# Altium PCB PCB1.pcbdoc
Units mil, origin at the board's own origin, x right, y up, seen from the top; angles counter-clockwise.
Board outline 2455.27 x 2908.05 mil, 4 copper layers (Top Layer, Inner1, Inner2, Bottom Layer); 58 components, 37 nets, 190 pads, 225 vias.
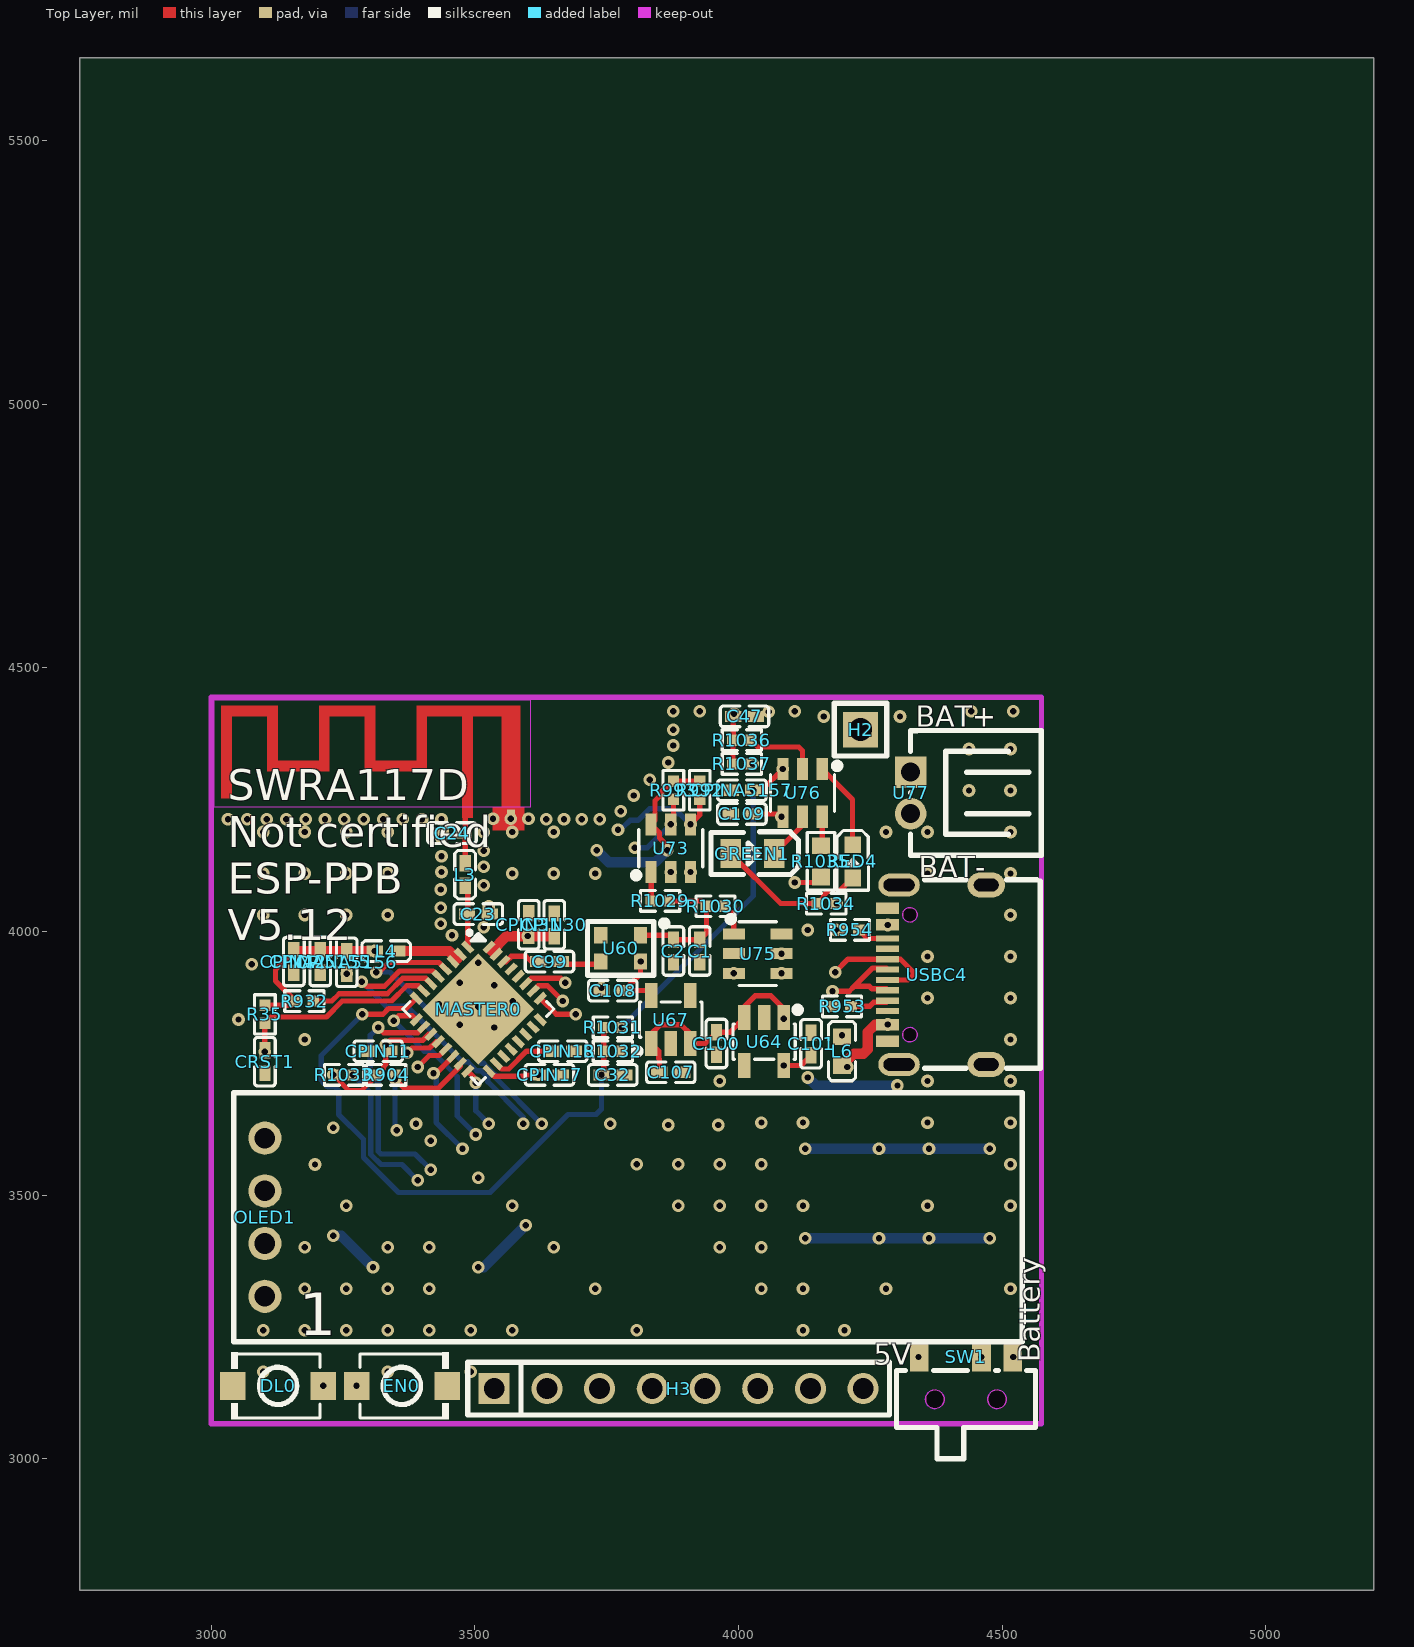
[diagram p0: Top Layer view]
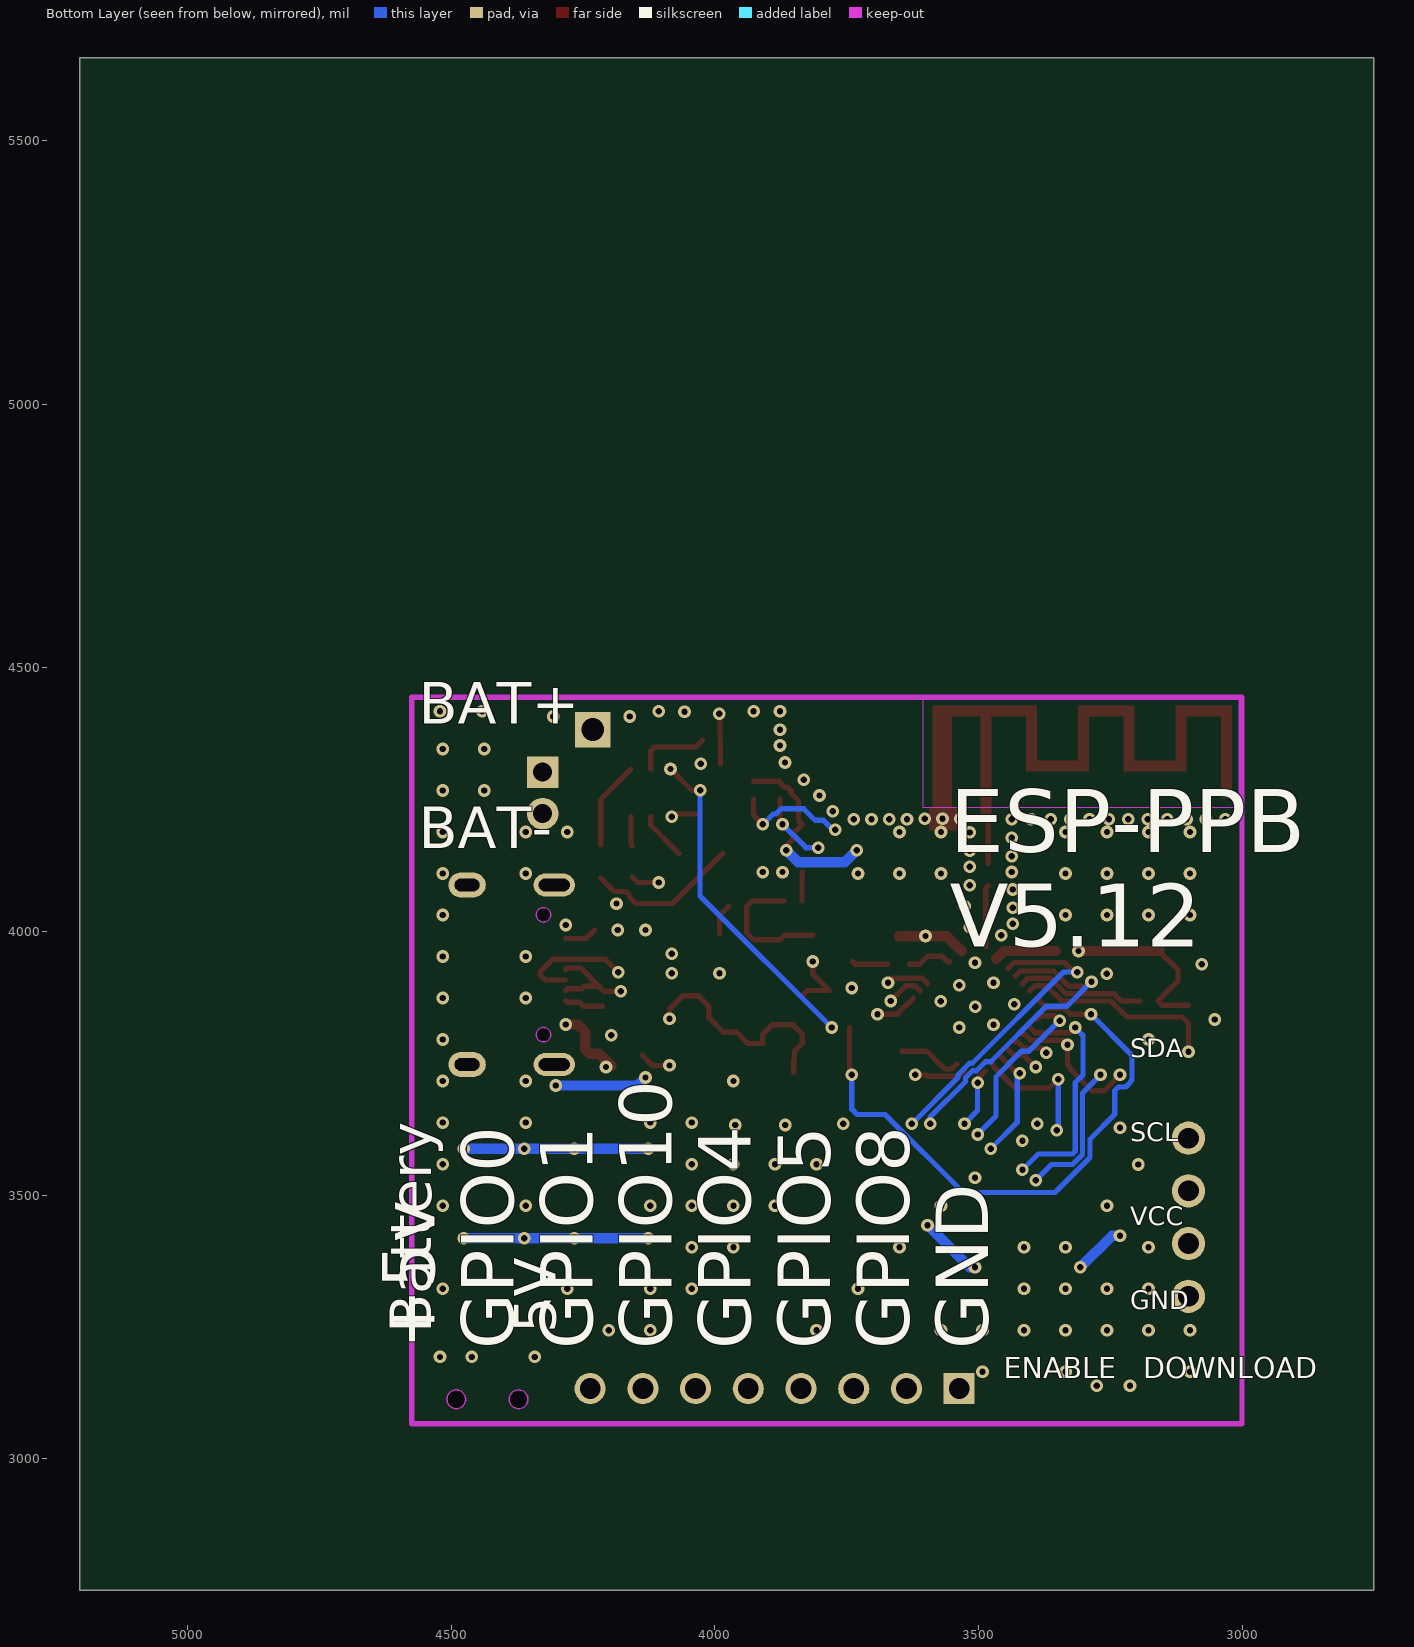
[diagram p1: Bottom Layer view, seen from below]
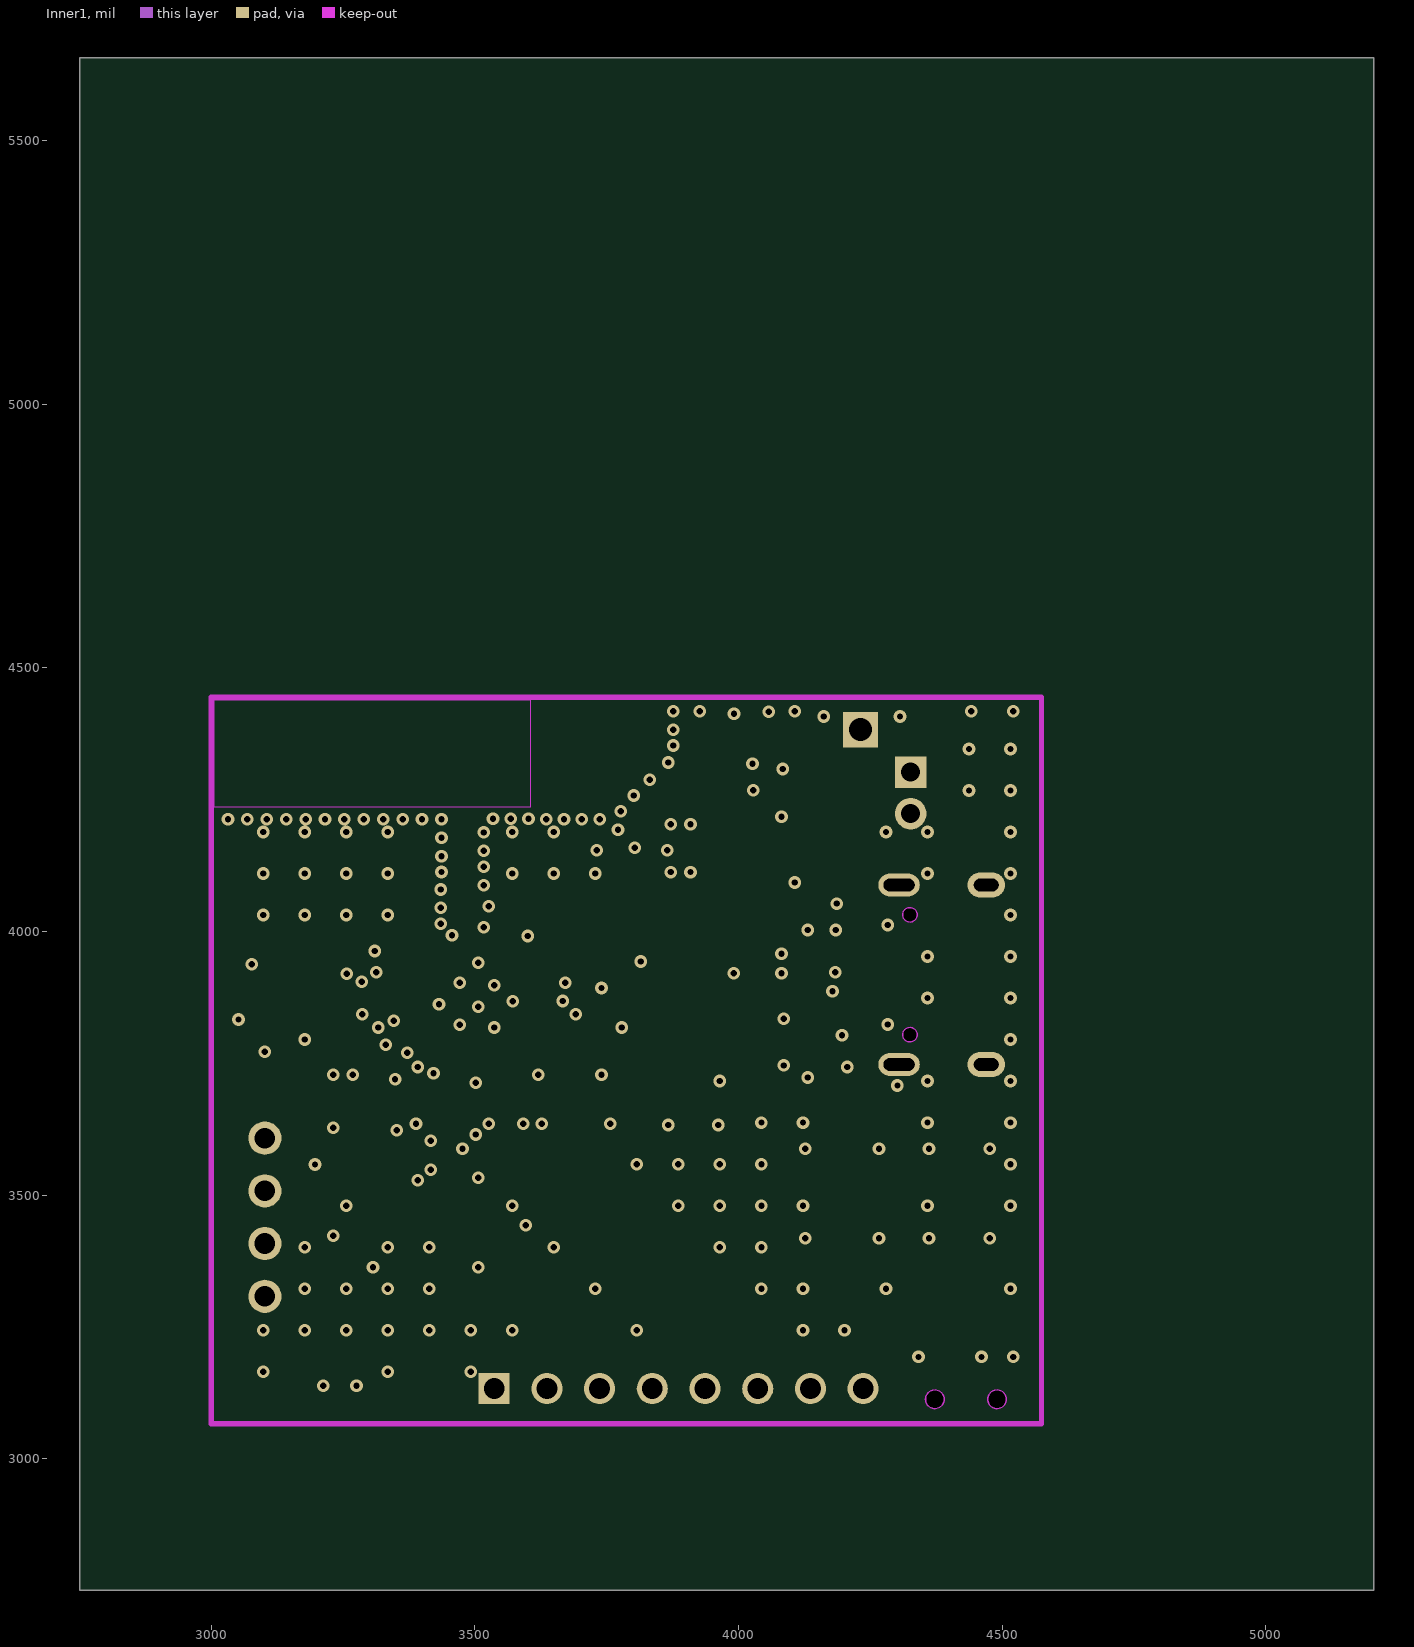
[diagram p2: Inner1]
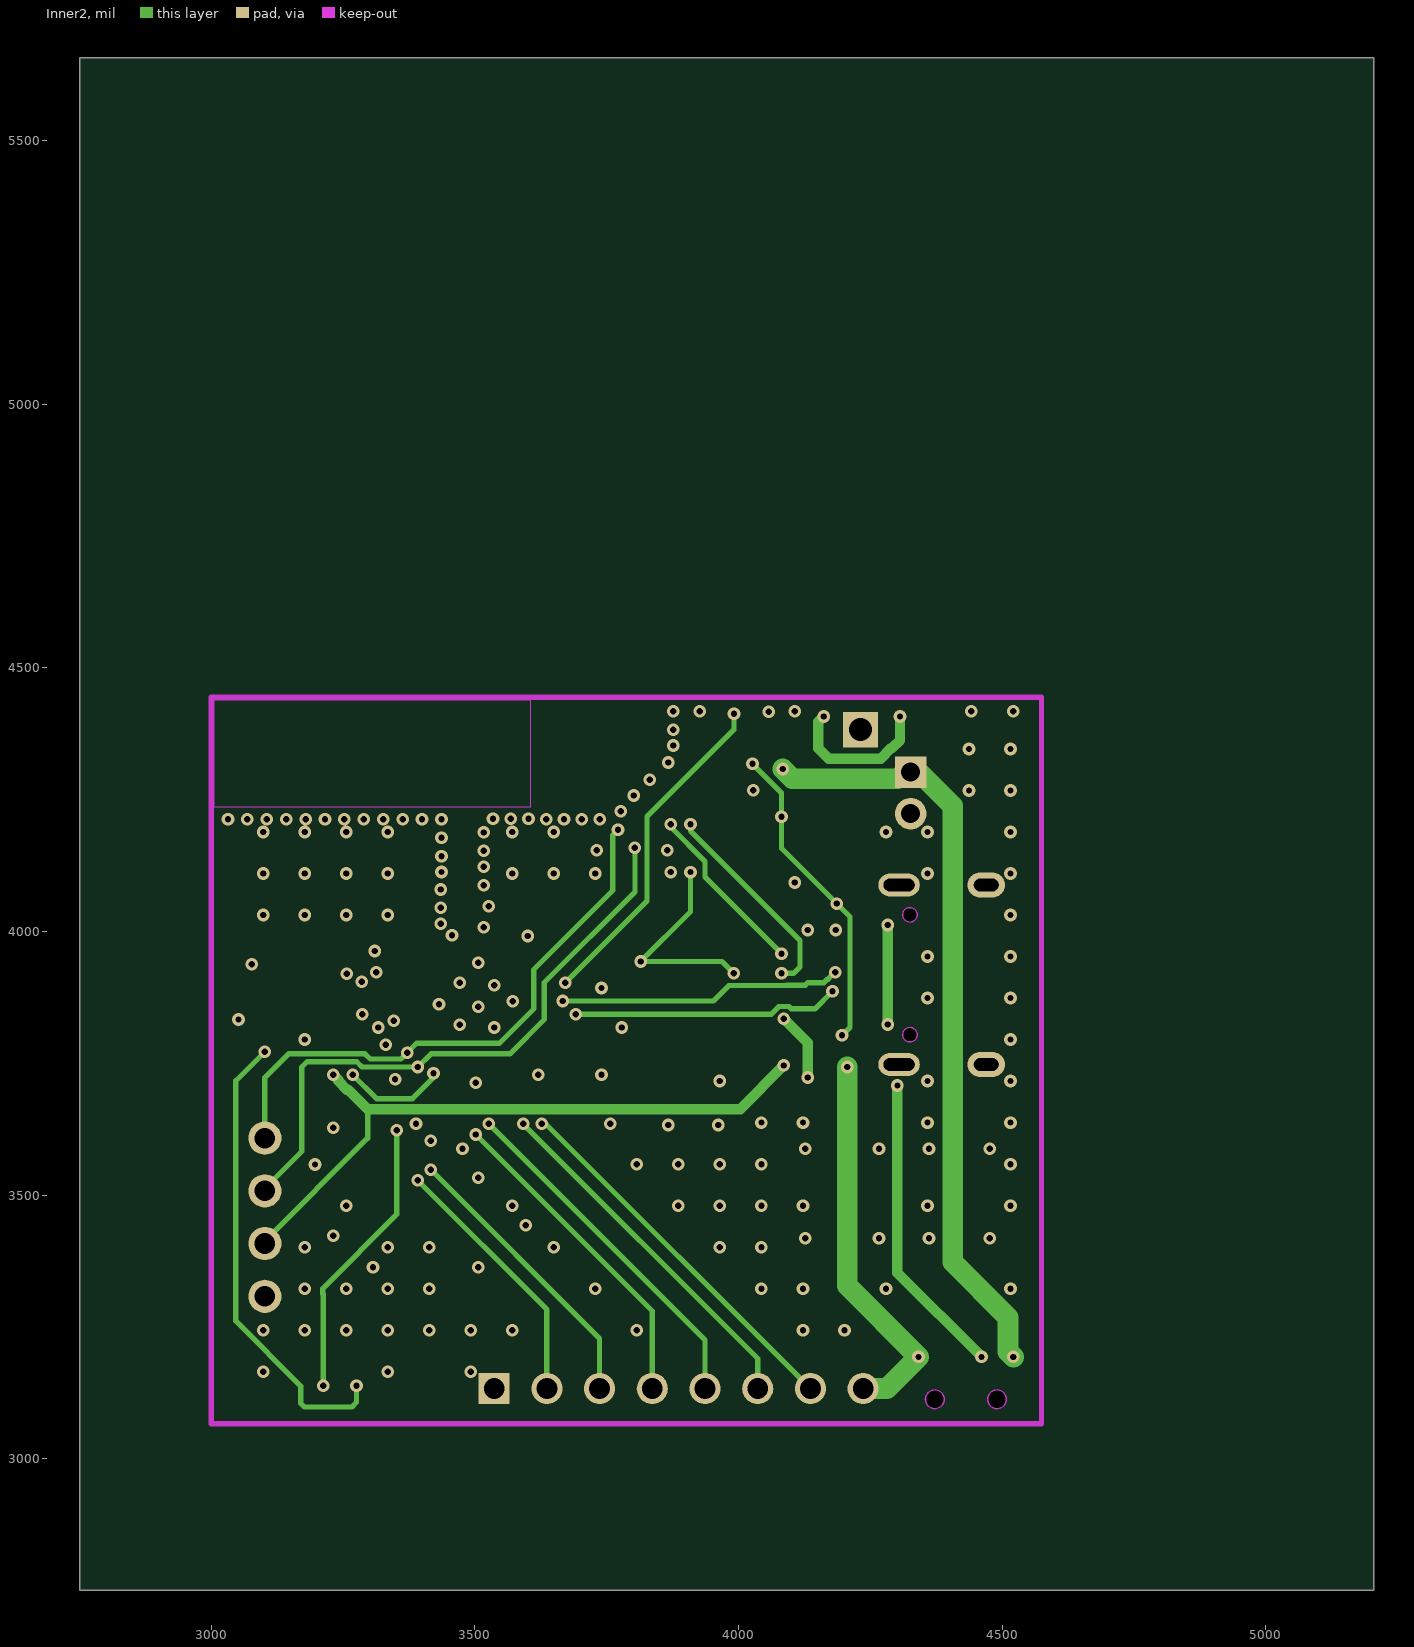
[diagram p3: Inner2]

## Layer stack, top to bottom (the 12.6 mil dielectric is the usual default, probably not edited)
Top Layer: signal copper (thickness not stored)
Dielectric: dielectric 12.6, FR-4, Dk 4.8
Inner1: signal copper (thickness not stored)
Dielectric: dielectric 12.6, FR-4, Dk 4.8
Inner2: signal copper (thickness not stored)
Dielectric: dielectric 12.6, FR-4, Dk 4.8
Bottom Layer: signal copper (thickness not stored)

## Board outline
5205.27,2750 2750,2750 2750,5658.05 5205.27,5658.05

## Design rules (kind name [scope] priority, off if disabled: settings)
BoardOutlineClearance copperThickness1oz [All] p0: genericclearance=10 ignorepadtopadclearanceinfootprint=FALSE except(0: Arc-SplitContinuation Track-SplitContinuation SMDPad-SplitContinuation THPad-SplitContinuation Via-SplitContinuation Fill-SplitContinuation Poly-SplitContinuation Region-SplitContinuation Text-SplitContinuation; 6: Track-CutoutEdge SMDPad-CutoutEdge THPad-CutoutEdge Via-CutoutEdge Region-CutoutEdge; 11.8: Track-OutlineEdge SMDPad-OutlineEdge THPad-OutlineEdge Via-OutlineEdge Fill-OutlineEdge Region-OutlineEdge Poly-OutlineEdge Text-OutlineEdge Fill-CutoutEdge)
BoardOutlineClearance copperThickness2oz [All] p0: genericclearance=10 ignorepadtopadclearanceinfootprint=FALSE except(0: Arc-SplitContinuation Track-SplitContinuation SMDPad-SplitContinuation THPad-SplitContinuation Via-SplitContinuation Fill-SplitContinuation Poly-SplitContinuation Region-SplitContinuation Text-SplitContinuation; 6: Track-CutoutEdge SMDPad-CutoutEdge THPad-CutoutEdge Via-CutoutEdge Region-CutoutEdge; 11.8: Track-OutlineEdge SMDPad-OutlineEdge THPad-OutlineEdge Via-OutlineEdge Fill-OutlineEdge Region-OutlineEdge Poly-OutlineEdge Text-OutlineEdge Fill-CutoutEdge)
Clearance copperThickness1oz [(InNet('GND') OR InNet('VCC') OR InNet('SDA') OR InNet('SCL') OR InNet('XTAL_P') OR InNet('FIVEHALF') OR InNet('DN') OR InNet('BATP') OR InNet('BATHALF') OR InNet('BATORFIVE') OR InNet('DP') OR InNet('+5V') OR InNet('$1N4007') OR InNet('$1N4019') OR InNet('$1N4047') OR InNet('$1N3990') OR InNet('$1N4052') OR InNet('$1N3999') OR InNet('$1N4001') OR InNet('$1N4004') OR InNet('$1N3976') OR InNet('$1N3977') OR InNet('$1N4056') OR InNet('$1N4584') OR InNet('$1N4585') OR InNet('$1N8525') OR InNet('$1N8521') OR InNet('$1N8933') OR InNet('$1N8476') OR InNet('$1N13130') OR InNet('GPIO8') OR InNet('GPIO10') OR InNet('GPIO5') OR InNet('GPIO4') OR InNet('GPIO1') OR InNet('GPIO0') OR InNet('VBUS'))] p1: gap=7 ignorepadtopadclearanceinfootprint=FALSE except(4: Track-Track; 6: Track-SMDPad SMDPad-SMDPad Track-THPad SMDPad-THPad THPad-THPad Track-Via SMDPad-Via THPad-Via Via-Via SMDPad-Fill THPad-Fill Via-Fill Fill-Fill Track-Region SMDPad-Region THPad-Region Via-Region Region-Region Track-Poly SMDPad-Poly THPad-Poly Via-Poly Fill-Poly Region-Poly Poly-Poly Track-Text SMDPad-Text THPad-Text Via-Text Fill-Text Region-Text Poly-Text Text-Text; 6.9: Track-Hole SMDPad-Hole THPad-Hole Via-Hole Fill-Hole Region-Hole Poly-Hole Text-Hole Sheet-Hole; 11.8: Track-Fill Fill-Region Track-Sheet SMDPad-Sheet THPad-Sheet Via-Sheet Fill-Sheet Region-Sheet Poly-Sheet Text-Sheet)
Clearance copperThickness2oz [All] p1: gap=7 ignorepadtopadclearanceinfootprint=FALSE except(6: Track-SMDPad SMDPad-SMDPad Track-THPad SMDPad-THPad THPad-THPad Track-Via SMDPad-Via THPad-Via Via-Via SMDPad-Fill THPad-Fill Via-Fill Fill-Fill Track-Region SMDPad-Region THPad-Region Via-Region Region-Region Track-Poly SMDPad-Poly THPad-Poly Via-Poly Fill-Poly Region-Poly Poly-Poly Track-Text SMDPad-Text THPad-Text Via-Text Fill-Text Region-Text Poly-Text Text-Text; 6.9: Track-Hole SMDPad-Hole THPad-Hole Via-Hole Fill-Hole Region-Hole Poly-Hole Text-Hole Sheet-Hole; 8: Track-Track; 11.8: Track-Fill Fill-Region Track-Sheet SMDPad-Sheet THPad-Sheet Via-Sheet Fill-Sheet Region-Sheet Poly-Sheet Text-Sheet)
DiffPairsRouting differentialPair [All] p1: maxuncoupledlength=10 minlimit=6 maxlimit=6 mostfreqgap=6 toplayer_minwidth=5 toplayer_prefwidth=10 toplayer_maxwidth=100 bottomlayer_minwidth=5 bottomlayer_prefwidth=10 bottomlayer_maxwidth=100 midlayer1_minwidth=5 midlayer1_prefwidth=10 midlayer1_maxwidth=100 midlayer2_minwidth=5 midlayer2_prefwidth=10 midlayer2_maxwidth=100
PasteMaskExpansion pasteMaskExpansion [All] p1: expansion=0
PlaneConnect innerPlane [All] p1: planeconnectstyle=Relief reliefexpansion=20 reliefentries=4 reliefconductorwidth=10 reliefairgap=10
PolygonConnect custom [All] p1: connectstyle=Direct reliefentries=4 reliefconductorwidth=10 polygonreliefangle="90 Angle" airgapwidth=10
RoutingVias viaSize [All] p1: viastyle="Through Hole" holewidth=12.0078 minholewidth=11.811 maxholewidth=248.0314 width=24.0158 minwidth=19.685 maxwidth=393.7008
SolderMaskExpansion solderMaskExpansion [All] p1: useseparateexpansions=TRUE expansion=2 expansionbottom=2
Width copperThickness1oz [All] p1: maxlimit=100 minlimit=5 preferedwidth=10
Width copperThickness2oz [All] p1: maxlimit=100 minlimit=8 preferedwidth=10

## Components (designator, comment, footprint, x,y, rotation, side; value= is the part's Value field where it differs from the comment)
C1 "CL05B104KB54PNC" C0402 3926.57,3963.05 r90 top
C2 "CL05A106MQ5NUNC" C0402 3876.57,3963.05 r90 top
C23 "GJM1555C1H1R5WB01D" C0402 3506.57,4033.05 r180 top
C24 "GJM1555C1H1R5WB01D" C0402 3456.65,4186.79 r0 top
C32 "CL05A106MQ5NUNC" C0402 3761.57,3728.05 r180 top
C47 "CL05A106MQ5NUNC" C0402 4011.57,4408.05 r180 top
C99 "0402CG470J500NT" C0402 3641.57,3943.05 r180 top
C100 "CL05A105KA5NQNC" C0402 3958.32,3787.58 r90 top
C101 "CL05A105KA5NQNC" C0402 4137.73,3786.91 r270 top
C107 "CL05A105KA5NQNC" C0402 3871.57,3733.05 r180 top
C108 "CL05A105KA5NQNC" C0402 3761.57,3888.05 r0 top
C109 "CL05A105KA5NQNC" C0402 4006.57,4223.05 r0 top
CPIN11 "CL05B104KB54PNC" C0402 3316.57,3773.05 r0 top
CPIN17 "CL05B104KB54PNC" C0402 3641.57,3728.05 r180 top
CPIN18 "CL05A105KA5NQNC" C0402 3666.57,3773.05 r0 top
CPIN30 "CL05A105KA5NQNC" C0402 3650.49,4012.87 r270 top
CPIN31 "CL05B103KB5NNNC" C0402 3602.12,4012.98 r270 top
CPINA2 "CL05B104KB54PNC" C0402 3156.57,3943.05 r90 top
CPINA5155 "CL05A105KA5NQNC" C0402 3206.57,3943.05 r90 top
CPINA5156 "CL05A106MQ5NUNC" C0402 3256.85,3941.52 r90 top
CPINA5157 "CL05A106MQ5NUNC" C0402 4006.57,4268.05 r0 top
CRST1 "CL05A105KA5NQNC" C0402 3101.57,3753.05 r90 top
DL0 "TS-1088-AR02016" SW-SMD_L3.9-W3.0-P4.45 3126.57,3138.05 r180 top
EN0 "TS-1088-AR02016" SW-SMD_L3.9-W3.0-P4.45 3361.57,3138.05 r0 top
GREEN1 "KT-0805G" LED0805-R-RD 4026.57,4148.05 r180 top
H2 "PZ254V-11-01P" HDR-TH_1P-P2.54-V-M 4231.57,4383.05 r0 top
H3 "B-2100S08P-A110" HDR-TH_8P-P2.54-V-M 3886.57,3133.05 r0 top
L3 "LQG15HS2N7S02D" L0402 3481.57,4108.05 r270 top
L4 "LQG15HS2N7S02D" L0402 3331.57,3963.05 r0 top
L6 "BLM18PG121SN1D_C14709" L0603 4196.57,3773.05 r90 top
MASTER0 "ESP32-C3FH4" QFN-32_L5.0-W5.0-P0.50-TL-EP3.7 3506.57,3853.05 r315 top
OLED1 "HS91L02W2C01" OLED-TH_L38.0-W12.0_HS91L02W2C01 3101.57,3458.05 r0 top
R35 "0402WGF1002TCE" R0402 3101.57,3843.05 r270 top
R904 "0402WGF1002TCE" R0402 3331.57,3728.05 r0 top
R932 "0402WGF1002TCE" R0402 3176.57,3868.05 r0 top
R953 "0402WGF5101TCE" R0402 4196.57,3858.05 r0 top
R954 "0402WGF5101TCE" R0402 4211.57,4003.05 r0 top
R992 "0402WGF4701TCE" R0402 3926.57,4268.05 r270 top
R993 "0402WGF4701TCE" R0402 3876.57,4268.05 r270 top
R1029 "0402WGF1003TCE" R0402 3851.57,4058.05 r0 top
R1030 "0402WGF3301TCE" R0402 3956.57,4048.05 r180 top
R1031 "0402WGF1003TCE" R0402 3761.57,3818.05 r0 top
R1032 "0402WGF1003TCE" R0402 3761.57,3773.05 r180 top
R1033 "0402WGF1002TCE" R0402 3251.57,3728.05 r0 top
R1034 "0402WGF1001TCE" R0402 4166.57,4053.05 r180 top
R1035 "0603WAF3901T5E" R0603 4156.57,4133.05 r270 top
R1036 "0402WGF2003TCE" R0402 4006.57,4363.05 r180 top
R1037 "0402WGF1003TCE" R0402 4006.57,4318.05 r0 top
RED4 "KT-0603R" LED0603-RD 4216.57,4133.05 r270 top
SW1 "MK-12C03-G015" SW-SMD_MK-12C03-G015 4431.57,3193.05 r0 top
U60 "TX0873AA12AE" CRYSTAL-SMD_4P-L2.5-W2.0-BL_TX0873AA12AE 3776.57,3968.05 r180 top
U64 "TPSPX3819M5-L-3-3" SOT-23-5_L3.0-W1.6-P0.95-LS2.8-BR 4048.82,3791.32 r90 top
U67 "TPSPX3819M5-L-3-3" SOT-23-5_L3.0-W1.6-P0.95-LS2.8-BR 3871.57,3833.05 r270 top
U73 "MCP4725A0T-E/CH" SOT-23-6_L2.9-W1.6-P0.95-LS2.8-BL 3871.57,4158.05 r0 top
U75 "MCP4725A0T-E/CH" SOT-23-6_L2.9-W1.6-P0.95-LS2.8-BL 4036.57,3958.05 r270 top
U76 "TP4057-42-SOT26-R" SOT-23-6_L2.9-W1.6-P0.95-LS2.8-BL 4121.57,4263.05 r180 top
U77 "WAFER-PH2.0-2PWZ" CONN-TH_2P-P2.00_GP01-2001WR-2P 4326.57,4263.05 r270 top
USBC4 "TYPE-C 16PIN 2MD(073)" USB-C-SMD_TYPE-C-6PIN-2MD-073 4376.57,3918.05 r90 top

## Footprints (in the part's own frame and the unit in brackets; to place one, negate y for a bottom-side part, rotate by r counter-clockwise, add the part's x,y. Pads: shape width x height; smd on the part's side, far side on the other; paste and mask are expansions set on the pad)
C0402 [mm]
  rect 0.79x0.54 smd: 1(-0.545,0) 2(0.545,0)
  silkscreen extent -1.17,-0.5 1.17,0.5
CONN-TH_2P-P2.00_GP01-2001WR-2P [mil]
  rect 60x60 hole 36: 1(-39.37,0)
  round 60 hole 36: 2(39.37,0)
  silkscreen extent -118,0 118,248
CRYSTAL-SMD_4P-L2.5-W2.0-BL_TX0873AA12AE [mm]
  rect 0.63x0.78 smd: 1(-0.96,-0.635) 2(0.96,-0.635) 3(0.96,0.635) 4(-0.96,0.635)
  silkscreen extent -2.25,-1.35 1.6,1.3
HDR-TH_1P-P2.54-V-M [mm]
  rect 1.7x1.7 hole 1.1: 1(0,0)
  silkscreen extent -1.27,-1.27 1.27,1.27
HDR-TH_8P-P2.54-V-M [mm]
  rect 1.5x1.5 hole 1: 1(-8.89,0)
  round 1.5 hole 1: 2(-6.35,0) 3(-3.81,0) 4(-1.27,0) 5(1.27,0) 6(3.81,0) 7(6.35,0) 8(8.89,0)
  silkscreen extent -10.16,-1.27 10.16,1.27
L0402 [mm]
  rect 0.79x0.54 smd: 1(-0.545,0) 2(0.545,0)
  silkscreen extent -1.17,-0.5 1.17,0.5
L0603 [mm]
  rect 0.8x0.864 smd: 1(-0.7,0) 2(0.7,0)
  silkscreen extent -1.42,-0.65 1.42,0.65
LED0603-RD [mm]
  rect 0.8x0.8 smd: 1(-0.799,0) 2(0.799,0)
  silkscreen extent -1.49,-0.75 1.39,0.76
LED0805-R-RD [mm]
  rect 1x1.4 smd: 1(1.05,0) 2(-1.05,0)
  silkscreen extent -2.22,-1.04 1.99,1.01
OLED-TH_L38.0-W12.0_HS91L02W2C01 [mm]
  round 1.6 hole 1: 1(0,-3.81) 2(0,-1.27) 3(0,1.27) 4(0,3.81)
  silkscreen extent -1.5,-6 36.5,6
QFN-32_L5.0-W5.0-P0.50-TL-EP3.7 [mm]
  rect 0.65x0.28 smd: 1(-2.478,1.75) 2(-2.478,1.25) 3(-2.478,0.75) 4(-2.478,0.25) 5(-2.478,-0.25) 6(-2.478,-0.75) 7(-2.478,-1.25) 8(-2.478,-1.75) 17(2.478,-1.75) 18(2.478,-1.25) 19(2.478,-0.75) 20(2.478,-0.25) 21(2.478,0.25) 22(2.478,0.75) 23(2.478,1.25) 24(2.478,1.75)
  rect 0.28x0.65 smd: 9(-1.75,-2.478) 10(-1.25,-2.478) 11(-0.75,-2.478) 12(-0.25,-2.478) 13(0.25,-2.478) 14(0.75,-2.478) 15(1.25,-2.478) 16(1.75,-2.478) 25(1.75,2.478) 26(1.25,2.478) 27(0.75,2.478) 28(0.25,2.478) 29(-0.25,2.478) 30(-0.75,2.478) 31(-1.25,2.478) 32(-1.75,2.478)
  rect 3.8x3.8 smd: 33(0,0)
  silkscreen extent -3,-2.58 2.58,2.58
R0402 [mm]
  rect 0.566x0.54 smd: 1(-0.433,0) 2(0.433,0)
  silkscreen extent -0.94,-0.5 0.94,0.5
R0603 [mil]
  rect 31.75x34.02 smd: 1(-29.66,0) 2(29.66,0)
  silkscreen extent -55,-26 55,26
SOT-23-5_L3.0-W1.6-P0.95-LS2.8-BR [mm]
  rect 1.2x0.6 smd: 1(1.15,-0.95) 2(1.15,0) 3(1.15,0.95) 4(-1.15,0.95) 5(-1.15,-0.95)
  silkscreen extent -0.85,-1.76 1.68,1.5
SOT-23-6_L2.9-W1.6-P0.95-LS2.8-BL [mil]
  rect 20.95x42.2 smd: 1(-37.4,-45.24) 2(0,-45.24) 3(37.4,-45.24) 4(37.4,45.24) 5(0,45.24) 6(-37.4,45.24)
  silkscreen extent -72,-57 61,35
SW-SMD_L3.9-W3.0-P4.45 [mm]
  rect 1.23x1.36 smd: 1(-2.185,0) 2(2.185,0)
  silkscreen extent -2.03,-1.62 2.25,1.62
SW-SMD_MK-12C03-G015 [mm]
  rect 0.9x1.4 smd: 1(-2.25,0) 2(0.75,0) 3(2.25,0)
  Board Outline Layer circle w0.005: c1.5,-2.042 r0.45
  Board Outline Layer circle w0.005: c-1.5,-2.042 r0.45
  Board Outline Layer region: 1.95,-2.042 1.905,-2.237 1.781,-2.394 1.6,-2.481 1.4,-2.481 1.219,-2.394 1.095,-2.237 1.05,-2.042 1.05,-2.042 1.095,-1.847 1.219,-1.69 1.4,-1.603 1.6,-1.603 1.781,-1.69 1.905,-1.847 1.95,-2.042
  Board Outline Layer region: -1.05,-2.042 -1.095,-2.237 -1.219,-2.394 -1.4,-2.481 -1.6,-2.481 -1.781,-2.394 -1.905,-2.237 -1.95,-2.042 -1.95,-2.042 -1.905,-1.847 -1.781,-1.69 -1.6,-1.603 -1.4,-1.603 -1.219,-1.69 -1.095,-1.847 -1.05,-2.042
  Multi-Layer board cut-out: 1.95,-2.042 1.905,-2.237 1.781,-2.394 1.6,-2.481 1.4,-2.481 1.219,-2.394 1.095,-2.237 1.05,-2.042 1.05,-2.042 1.095,-1.847 1.219,-1.69 1.4,-1.603 1.6,-1.603 1.781,-1.69 1.905,-1.847 1.95,-2.042
  Multi-Layer board cut-out: -1.05,-2.042 -1.095,-2.237 -1.219,-2.394 -1.4,-2.481 -1.6,-2.481 -1.781,-2.394 -1.905,-2.237 -1.95,-2.042 -1.95,-2.042 -1.905,-1.847 -1.781,-1.69 -1.6,-1.603 -1.4,-1.603 -1.219,-1.69 -1.095,-1.847 -1.05,-2.042
  silkscreen extent -3.35,-4.9 3.35,-0.65
USB-C-SMD_TYPE-C-6PIN-2MD-073 [mm]
  rect 0.55x1.1 smd: 1(-3.2,2.375) 2(-2.4,2.375) 11(2.4,2.375) 12(3.2,2.375)
  rect 0.3x1.1 smd: 3(-1.75,2.375) 4(-1.25,2.375) 5(-0.75,2.375) 6(-0.25,2.375) 7(0.25,2.375) 8(0.75,2.375) 9(1.25,2.375) 10(1.75,2.375)
  oval 1.2x1.8 hole 0.6 slot 1.2 at 90 deg: 13(-4.325,-2.375) 14(4.325,-2.375)
  oval 1.1x2 hole 0.6 slot 1.5 at 90 deg: 13(-4.325,1.825) 14(4.325,1.825)
  Board Outline Layer circle w0.005: c-2.89,1.305 r0.35
  Board Outline Layer circle w0.005: c2.89,1.305 r0.35
  Board Outline Layer region: -2.89,0.955 -3.042,0.99 -3.164,1.087 -3.231,1.227 -3.231,1.383 -3.164,1.523 -3.042,1.62 -2.89,1.655 -2.89,1.655 -2.738,1.62 -2.616,1.523 -2.549,1.383 -2.549,1.227 -2.616,1.087 -2.738,0.99 -2.89,0.955
  Board Outline Layer region: 2.89,0.955 2.738,0.99 2.616,1.087 2.549,1.227 2.549,1.383 2.616,1.523 2.738,1.62 2.89,1.655 2.89,1.655 3.042,1.62 3.164,1.523 3.231,1.383 3.231,1.227 3.164,1.087 3.042,0.99 2.89,0.955
  Multi-Layer board cut-out: -2.89,0.955 -3.042,0.99 -3.164,1.087 -3.231,1.227 -3.231,1.383 -3.164,1.523 -3.042,1.62 -2.89,1.655 -2.89,1.655 -2.738,1.62 -2.616,1.523 -2.549,1.383 -2.549,1.227 -2.616,1.087 -2.738,0.99 -2.89,0.955
  Multi-Layer board cut-out: 2.89,0.955 2.738,0.99 2.616,1.087 2.549,1.227 2.549,1.383 2.616,1.523 2.738,1.62 2.89,1.655 2.89,1.655 3.042,1.62 3.164,1.523 3.231,1.383 3.231,1.227 3.164,1.087 3.042,0.99 2.89,0.955
  silkscreen extent -4.5,-4.97 4.57,0.6

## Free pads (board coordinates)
  rect 15.75x15.75 smd: GND(3568.51,4223.4)

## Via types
v1: diameter 24.02, hole 12.01, Top Layer to Bottom Layer, 225 vias

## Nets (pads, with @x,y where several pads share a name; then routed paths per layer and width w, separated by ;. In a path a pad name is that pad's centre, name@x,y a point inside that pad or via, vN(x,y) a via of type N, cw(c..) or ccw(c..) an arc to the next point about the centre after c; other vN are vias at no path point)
$1N3976: R953.2 USBC4.4 | length 73.9
  Top Layer w10: R953.2 4248.87,3858.05 4256.86,3866.05 4280.27,3866.05 USBC4.4
$1N3977: R954.2 USBC4.10 | length 61.1
  Top Layer w10: R954.2 4244.71,3986.96 USBC4.10
$1N3990: CPIN18.1 MASTER0.18 | length 122.5
  Top Layer w10: MASTER0.18 3550.76,3739.27 3564.36,3739.27 3598.14,3773.05 CPIN18.1
$1N3999: DL0.1 MASTER0.15 R904.2 | length 794.3
  Top Layer w10: v1(3348.61,3720.06) 3365.62,3703.05 3430.68,3703.05 3472.4,3744.77 MASTER0.15
  Inner2 w10: v1(3212.59,3138.05) 3212.59,3312.03 3211.57,3313.05 3211.57,3323.05 3351.57,3463.05 v1(3351.57,3623.05)
  Bottom Layer w10: v1(3348.61,3720.06) 3348.61,3626.01 v1(3351.57,3623.05)
$1N4001: L4.2 MASTER0.2 MASTER0.3 | length 119.8
  Top Layer w19.68: L4.2 3451.57,3963.05 3466.57,3948.05
$1N4004: MASTER0.6 R932.2 | length 245.2
  Top Layer w10: R932.2 3228.57,3868.05 3242.59,3882.07 3333.83,3882.07 3363.01,3911.25 3406.61,3911.25 MASTER0.6
$1N4007: C23.2 L3.2 MASTER0.1 | length 117.8
  Top Layer w10: L3.2 3486.32,4081.84 MASTER0.1
$1N4019: C24.2 L3.1 | length 88.5
  Top Layer w10: L3.1 3481.57,4218.05
$1N4047: C99.1 U60.3 | length 67.8
  Top Layer w10: C99.1@3673.03,3938.05 3733.78,3938.05 U60.3
$1N4052: CRST1.2 EN0.1 MASTER0.7 R35.2 | length 1270.6
  Top Layer w10: CRST1.2 R35.2 3113.53,3837.97 3218.31,3837.97 3248.39,3868.05 3341.57,3868.05 3370.75,3897.23 3392.8,3897.23 MASTER0.7
  Inner2 w10: v1(3101.57,3771.95) 3046.57,3716.95 3046.57,3260.98 3169.5,3138.05 3169.5,3105.12 3176.57,3098.05 3266.57,3098.05 3275.55,3107.03 v1(3275.55,3138.05)
$1N4056: C108.2 U60.4 U67.5 U73.3 U75.3 | length 518.3
  Top Layer w10: v1(3814.37,3943.05) 3814.37,3919.39 C108.2 3824.45,3888.05 U67.5
  Inner2 w10: v1(3908.97,4112.81) 3908.97,4037.66 v1(3814.37,3943.05) 3968.93,3943.05 v1(3991.33,3920.65)
$1N4584: R1029.1 U73.1 | length 54.9
  Top Layer w10: U73.1 3834.53,4112.45 R1029.1
$1N4585: R1030.1 U75.1 | length 59.9
  Top Layer w10: R1030.1 3991.33,4030.33 U75.1
$1N8476: RED4.1 U76.1 | length 167.6
  Top Layer w10: U76.1 4216.57,4250.7 RED4.1
$1N8521: GREEN1.1 R1034.2 RED4.2 | length 292.7
  Top Layer w10: GREEN1.1 4080.22,4053.05 R1034.2 4161.49,4065.01 4161.49,4068.23 4169.3,4076.05 4191.04,4076.05 RED4.2
$1N8525: GREEN1.2 U76.5 | length 92
  Top Layer w10: GREEN1.2 4121.57,4201.7 U76.5
$1N8933: R1035.1 U76.6 | length 56.1
  Top Layer w10: R1035.1 4158.97,4165.11 U76.6
$1N13130: C1.2 C2.2 R1029.2 R1030.2 U60.1 | length 259.7
  Top Layer w10: U60.1 3868.03,3993.05 C2.2 C1.2 3939.53,3997.47 R1030.2 3929.53,4058.05 R1029.2
+5V: C109.2 L6.2 R1034.1 R1037.2 U76.4 | length 653.5
  Top Layer w10: C109.2 4076.57,4223.05 v1(4081.57,4218.05)
  Inner2 w10: v1(4026.57,4318.05) 4081.57,4263.05 v1(4081.57,4218.05) 4081.57,4158.05 v1(4186.57,4053.05) 4211.57,4028.05 4211.57,3818.05 v1(4196.57,3803.05)
BATHALF: C32.2 MASTER0.8 R1031.1 R1032.2 | length 1161.6
  Top Layer w10: v1(3286.57,3843.05) 3325.42,3843.05 3336.41,3854.04 3369.61,3854.04 MASTER0.8 ; v1(3740.11,3728.05) 3744.53,3732.47 R1032.2 R1031.1
  Bottom Layer w10: v1(3286.57,3843.05) 3208.58,3765.06 3208.58,3718.53 3212.41,3714.7 3212.41,3712.87 3218.85,3706.44 3220.67,3706.44 3222.05,3705.06 3234.48,3705.06 3241.57,3697.97 3241.57,3653.05 3288.54,3606.08 3288.54,3571.44 3354.92,3505.06 3528.93,3505.06 3676.92,3653.05 3730.11,3653.05 3740.11,3663.05 v1(3740.11,3728.05)
BATORFIVE: C100.2 C107.2 SW1.2 U64.1 U64.3 U67.1 U67.3 | length 1330.1
  Top Layer w10: C107.2 3850.11,3758.27 3848.78,3759.61 3848.78,3773.17 U67.1 3834.17,3805.65 3851.57,3823.05 3891.57,3823.05 3908.97,3805.65 U67.3 3937.06,3787.78 C100.2 3983.87,3809.04 U64.3 4011.42,3857.9 4031.57,3878.05 4061.57,3878.05 4086.22,3853.4 v1(4086.22,3834.63)
  Inner2 w19.68: v1(4086.22,3834.63) 4131.57,3789.28 v1(4131.57,3723.05) ; v1(4301.57,3708.05) 4301.57,3352.59 v1(4461.11,3193.05)
  Bottom Layer w19.68: v1(4131.57,3723.05) 4146.57,3708.05 v1(4301.57,3708.05)
BATP: CPINA5157.2 R1031.2 SW1.3 U76.3 U77.1 | length 2077.4
  Top Layer w10: v1(4028.03,4268.05) 4043.93,4268.05 v1(4084.17,4308.29)
  Inner2 w39.37: v1(4084.17,4308.29) 4102.71,4289.76 4302.16,4289.76 U77.1@4320.7,4308.29 ; U77.1 4331.57,4297.42 4347.2,4297.42 4406.57,4238.05 4406.57,3373.05 4511.57,3268.05 4511.57,3203.05 v1(4521.57,3193.05)
  Bottom Layer w10: v1(3778.32,3818.05) 4028.03,4067.77 v1(4028.03,4268.05)
DN: MASTER0.25 USBC4.5 USBC4.7 | length 778.8
  Top Layer w10: MASTER0.25 3654.26,3843.3 v1(3691.57,3843.3) ; v1(4178.42,3886.68) 4210.19,3886.68 4219.49,3895.97 ; USBC4.5 4280.28,3891.32 4253.31,3891.32 4248.65,3895.97 4219.49,3895.97 ; USBC4.7 4280.28,3930.69 4254.21,3930.69 4219.49,3895.97
  Inner2 w10: v1(3691.57,3843.3) 4062.38,3843.3 4076.7,3857.62 4095.74,3857.62 4100.06,3853.3 4145.05,3853.3 v1(4178.42,3886.68)
DP: MASTER0.26 USBC4.6 USBC4.8 | length 837.9
  Top Layer w10: MASTER0.26 3620.35,3897.23 3637.64,3897.23 v1(3666.57,3868.3) ; v1(4183.58,3923.05) 4208.1,3947.58 USBC4.8 4307.05,3947.58 4331.57,3923.05 4331.57,3918.05 4321.73,3908.21 USBC4.6
  Inner2 w10: v1(3666.57,3868.3) 3952.45,3868.3 3981.81,3897.66 4091.33,3897.66 4091.73,3898.05 4126.57,3898.05 4131.57,3903.05 4162.28,3903.05 4168.9,3909.67 4170.19,3909.67 v1(4183.58,3923.05)
FIVEHALF: C47.2 MASTER0.27 R1036.2 R1037.1 | length 815.5
  Top Layer w10: MASTER0.27 3606.53,3911.25 3663.37,3911.25 v1(3671.57,3903.05) ; R1037.1 R1036.2 3990.11,4363.63 C47.2
  Inner2 w10: v1(3671.57,3903.05) 3826.57,4058.05 3826.57,4218.05 3991.57,4383.05 v1(3991.57,4413.05)
GND: C1.1 C2.1 C23.1 C24.1 C32.1 C47.1 C100.1 C101.1 C107.1 C108.1 C109.1 CPIN11.1 CPIN17.1 CPIN18.2 CPIN30.1 CPIN31.1 CPINA2.1 CPINA5155.1 CPINA5156.1 CPINA5157.1 CRST1.1 DL0.2 EN0.2 H2.1 H3.1 MASTER0.33 OLED1.1 pad.GND R953.1 R954.1 R1032.1 R1035.2 R1036.1 U60.2 U64.2 U67.2 U73.2 U75.2 U75.6 U76.2 U77.2 USBC4.1 USBC4.12 USBC4.13 USBC4.14 | length 195.3
  Top Layer w10: R1036.1 4036.54,4350.12 4114.5,4350.12 4121.57,4343.05 U76.2 ; v1(4106.57,4093.05) 4146.23,4093.05 R1035.2
  other v1: 3098.68,3165.16 3334.9,3165.16 3492.38,3165.16 3098.68,3243.9 3177.42,3243.9 3256.16,3243.9 3334.9,3243.9 3413.64,3243.9 3492.38,3243.9 3571.12,3243.9 3807.34,3243.9 4122.31,3243.9 4201.05,3243.9 3177.42,3322.64 3256.16,3322.64 3334.9,3322.64 3413.64,3322.64 3728.6,3322.64 4043.57,3322.64 4122.31,3322.64 4279.79,3322.64 4516.01,3322.64 3177.42,3401.38 3334.9,3401.38 3413.64,3401.38 3649.86,3401.38 3964.82,3401.38 4043.57,3401.38 3256.16,3480.12 3571.12,3480.12 3886.08,3480.12 3964.82,3480.12 4043.57,3480.12 4122.31,3480.12 4358.53,3480.12 4516.01,3480.12 3506.57,3533.05 3196.57,3558.05 3807.34,3558.86 3886.08,3558.86 3964.82,3558.86 4043.57,3558.86 4516.01,3558.86 3416.57,3603.05 3231.57,3628.05 3866.57,3633.05 3961.57,3633.05 3388.16,3635.22 3756.57,3635.22 4043.57,3637.6 4122.31,3637.6 4358.53,3637.6 4516.01,3637.6 3964.82,3716.34 4358.53,3716.34 4516.01,3716.34 3177.42,3795.08 4516.01,3795.08 3536.57,3818.05 3471.41,3822.89 3051.57,3833.05 3506.17,3857.16 3432,3862.31 3571.57,3868.05 4358.53,3873.82 4516.01,3873.82 3740.11,3893.05 3536.57,3898.05 3471.57,3903.05 3256.85,3920.06 3076.57,3938.05 3506.57,3940.94 4358.53,3952.56 4516.01,3952.56 3456.57,3993.05 4131.57,4003.05 4184.53,4003.05 3516.57,4008.05 3435.11,4014.89 3098.68,4031.3 3177.42,4031.3 3256.16,4031.3 3334.9,4031.3 4516.01,4031.3 3435.11,4044.89 3526.57,4048.05 3435.11,4079.89 3516.57,4088.05 3098.68,4110.04 3177.42,4110.04 3256.16,4110.04 3334.9,4110.04 3571.12,4110.04 3649.86,4110.04 3728.6,4110.04 4358.53,4110.04 4516.01,4110.04 3436.57,4113.05 3871.57,4112.81 3516.57,4123.05 3436.57,4143.05 3516.57,4153.05 3436.57,4178.05 3516.57,4188.05 3098.68,4188.78 3177.42,4188.78 3256.16,4188.78 3334.9,4188.78 3571.12,4188.78 3649.86,4188.78 4279.79,4188.78 4358.53,4188.78 4516.01,4188.78 3031.57,4213.05 3068.39,4213.05 3105.21,4213.05 3142.03,4213.05 3178.84,4213.05 3215.66,4213.05 3252.48,4213.05 3289.3,4213.05 3326.12,4213.05 3362.93,4213.05 3399.75,4213.05 3436.57,4213.05 3635.46,4213.05 3669.17,4213.05 3702.87,4213.05 3736.57,4213.05 3534.35,4213.68 3568.06,4213.68 3601.76,4213.68 3776.57,4228.05 3801.57,4258.05 4437.27,4267.52 4516.01,4267.52 3831.57,4288.05 3866.94,4320.62 4437.27,4346.26 4516.01,4346.26 3876.57,4353.05 3876.57,4383.05 4057.58,4416.68 3876.57,4418.05 3926.57,4418.05 4106.57,4418.05 4441.57,4418.05 4521.57,4418.05
GPIO0: H3.7 MASTER0.4 | length 1298.6
  Top Layer w10: v1(3312.8,3923.05) 3318.19,3923.05 3336.57,3941.44 3432.1,3941.44 MASTER0.4
  Inner2 w10: v1(3626.57,3635.22) 3634.41,3635.22 H3.7
  Bottom Layer w10: v1(3312.8,3923.05) 3338.74,3923.05 3511.73,3750.06 3516.9,3750.06 3538.58,3728.38 3538.58,3723.21 v1(3626.57,3635.22)
GPIO1: H3.6 MASTER0.5 | length 1281.5
  Top Layer w10: v1(3285.47,3905.06) 3294.44,3896.08 3328.02,3896.08 3357.2,3925.27 3420.44,3925.27 MASTER0.5
  Inner2 w10: v1(3591.57,3635.22) 4036.57,3190.22 H3.6
  Bottom Layer w10: v1(3285.47,3905.06) 3332.48,3858.05 3371.57,3858.05 3476.57,3753.05 3486.57,3753.05 3503.58,3736.05 3511.09,3736.05 3524.56,3722.58 3524.56,3715.06 3591.57,3648.05 v1(3591.57,3635.22)
GPIO4: H3.4 MASTER0.9 | length 959.2
  Top Layer w10: v1(3345.93,3831.05) 3354.91,3840.02 3381.66,3840.02 MASTER0.9
  Inner2 w10: v1(3501.57,3615.12) 3836.57,3280.12 H3.4
  Bottom Layer w10: v1(3345.93,3831.05) 3403.92,3773.05 3418.07,3773.05 3466.57,3724.55 3466.57,3650.12 v1(3501.57,3615.12)
GPIO5: H3.3 MASTER0.10 | length 1004.3
  Top Layer w10: v1(3316.58,3818.05) 3326.58,3808.05 3391.98,3808.05 MASTER0.10
  Inner2 w10: v1(3416.57,3548.05) 3736.57,3228.05 H3.3
  Bottom Layer w10: v1(3316.58,3818.05) 3301.57,3803.05 3301.57,3728.05 3316.58,3713.05 3316.58,3583.05 3321.57,3578.05 3386.57,3578.05 v1(3416.57,3548.05)
GPIO8: H3.2 MASTER0.14 R1033.2 | length 1183.3
  Top Layer w10: v1(3421.57,3731.05) 3426.32,3731.05 MASTER0.14
  Inner2 w10: v1(3268.32,3728.05) 3313.32,3683.05 3381.57,3683.05 3421.57,3723.05 v1(3421.57,3731.05) ; v1(3391.57,3528.05) 3636.57,3283.05 H3.2
  Bottom Layer w10: v1(3268.32,3728.05) 3302.56,3693.81 3302.56,3577.24 3321.75,3558.05 3361.57,3558.05 v1(3391.57,3528.05) ; v1(3421.57,3731.05) 3426.57,3726.05 3426.57,3638.05 v1(3476.57,3588.05)
GPIO10: H3.5 MASTER0.16 | length 788.8
  Top Layer w10: MASTER0.16 3501.57,3720.11 v1(3501.57,3713.05)
  Inner2 w10: v1(3526.57,3635.22) 3936.57,3225.22 H3.5
  Bottom Layer w10: v1(3501.57,3713.05) 3501.57,3660.22 v1(3526.57,3635.22)
SCL: MASTER0.13 OLED1.3 R993.2 U73.5 U75.5 | length 1697.4
  Top Layer w10: v1(3391.57,3743.05) 3413.54,3765.02 3432.46,3765.02 MASTER0.13 ; v1(3871.57,4203.29) 3876.57,4208.29 R993.2
  Inner2 w10: OLED1.3@3101.57,3513.05 3171.57,3583.05 3171.57,3743.05 3181.57,3753.05 3275.83,3753.05 3285.83,3743.05 v1(3391.57,3743.05) 3416.57,3768.05 3566.57,3768.05 3631.57,3833.05 3631.57,3903.05 3803.58,4075.06 v1(3803.58,4159.16) ; v1(3871.57,4203.29) 3871.57,4198.05 3936.57,4133.05 3936.57,4103.29 v1(4081.81,3958.05)
  Bottom Layer w10: v1(3803.58,4159.16) 3827.44,4159.16 v1(3871.57,4203.29)
SDA: MASTER0.12 OLED1.4 R992.2 U73.4 U75.4 | length 1773.6
  Top Layer w10: v1(3371.58,3770.06) 3380.55,3779.04 3414.12,3779.04 3426.13,3791.04 MASTER0.12 ; v1(3908.97,4203.29) 3926.57,4220.89 R992.2
  Inner2 w10: OLED1.4@3101.57,3613.05 3101.57,3723.05 3146.57,3768.05 3291.57,3768.05 3301.57,3758.05 3359.57,3758.05 v1(3371.58,3770.06) 3389.57,3788.05 3546.57,3788.05 3611.57,3853.05 3611.57,3928.05 3761.57,4078.05 3761.57,4183.05 v1(3771.57,4193.05) ; v1(3908.97,4203.29) 3908.97,4190.65 4116.57,3983.05 4116.57,3933.05 4104.17,3920.65 v1(4081.81,3920.65)
  Bottom Layer w10: v1(3771.57,4193.05) 3776.03,4197.52 3780.59,4197.52 3794.06,4210.98 3809.5,4210.98 3831.57,4233.05 3874.33,4233.05 3884.33,4223.05 3889.21,4223.05 v1(3908.97,4203.29)
VBUS: H3.8 L6.1 SW1.1 USBC4.2 USBC4.11 | length 1062.6
  Top Layer w19.68: L6.1 4219.13,3768.05 4236.57,3768.05 4245.59,3777.07 4245.59,3809.45 4259.7,3823.57 v1(4283.07,3823.57)
  Inner2 w19.68: v1(4283.07,3823.57) v1(4283.07,4012.55)
  Inner2 w39.37: v1(4206.57,3743.05) 4206.57,3328.05 v1(4341.57,3193.05) 4281.57,3133.05 H3.8
VCC: C101.2 CPIN11.2 CPIN17.2 CPIN30.2 CPIN31.2 CPINA2.2 CPINA5155.2 CPINA5156.2 L4.1 MASTER0.11 MASTER0.17 MASTER0.31 MASTER0.32 OLED1.2 R35.1 R904.1 R932.1 R992.1 R993.1 R1033.1 U64.5 U73.6 | length 3722
  Top Layer w10: R35.1 3151.57,3860.09 R932.1 3121.57,3906.01 3121.57,3928.31 3141.39,3948.13 3143.11,3948.13 CPINA2.2@3158.03,3963.05 ; v1(3231.57,3728.05) 3246.49,3713.13 3246.49,3712.87 3261.31,3698.05 3284.53,3698.05 R904.1 3326.49,3740.01 3326.49,3743.23 3331.02,3747.76 v1(3331.02,3785.06) 3339.99,3794.04 3401.29,3794.04 3412.22,3804.96 MASTER0.11 ; MASTER0.17 3536.93,3725.26 3595.42,3725.26 3598.22,3728.05 v1(3620.11,3728.05) ; v1(3864.62,4154.22) 3864.62,4163.13 3850.11,4177.64 3850.11,4187.35 U73.6 3841.57,4210.69 3841.57,4248.05 3854.96,4261.44 3854.96,4266.7 3861.39,4273.13 3866.65,4273.13 3876.57,4283.05 R993.1 R992.1 ; v1(4086.22,3746.04) 4118.32,3746.04 C101.2
  Top Layer w19.68: CPINA2.2 3158.03,3963.05 3256.85,3963.05 v1(3310.11,3963.05) ; 3531.57,3963.05 3559.93,3991.41 v1(3600.49,3991.41) CPIN30.2
  Inner2 w10: OLED1.2@3101.57,3413.05 3296.57,3608.05 3296.57,3663.05
  Inner2 w19.68: v1(3231.57,3728.05) 3240.48,3719.14 3240.48,3716.52 3256.79,3700.22 3259.41,3700.22 3296.57,3663.05 4003.23,3663.05 v1(4086.22,3746.04) ; v1(4161.57,4408.05) 4151.57,4398.05 4151.57,4347.74 4171.26,4328.05 4269.82,4328.05 4290.02,4348.25 4291.77,4348.25 4306.57,4363.05 v1(4306.57,4408.05)
  Bottom Layer w19.68: v1(3231.57,3423.05) 3246.57,3423.05 v1(3306.57,3363.05) ; v1(3506.57,3363.05) 3516.57,3363.05 v1(3596.57,3443.05) ; v1(3730.89,4154.22) 3753.78,4131.32 3841.73,4131.32 v1(3864.62,4154.22) ; v1(4126.57,3418.05) v1(4266.57,3418.05) v1(4361.57,3418.05) v1(4476.57,3418.05) ; v1(4126.57,3588.05) v1(4266.57,3588.05) v1(4361.57,3588.05) v1(4476.57,3588.05)
XTAL_P: C99.2 MASTER0.30 | length 85.9
  Top Layer w10: MASTER0.30 3559.18,3942.91 3569.18,3952.91 3586.43,3952.91 3586.57,3953.05 3596.57,3953.05 3611.57,3938.05 C99.2@3630.11,3938.05
pads on no net: MASTER0.19 MASTER0.20 MASTER0.21 MASTER0.22 MASTER0.23 MASTER0.24 MASTER0.28 MASTER0.29 U64.4 U67.4 USBC4.3 USBC4.9

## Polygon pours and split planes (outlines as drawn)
GND on Top Layer (solid, remove dead copper, pour order 0): 3005.12,4235.37 3758.89,4235.37 3856.57,4333.05 3856.57,4438.05 4567.68,4438.05 4567.68,3072.2 3006.35,3072.2
GND on Inner1 (solid, remove dead copper): 3005.12,4235.37 3759.19,4235.37 3856.57,4330.69 3856.57,4435.69 4567.68,4435.69 4567.68,3069.83 3006.35,3069.83
VCC on Inner2 (solid, remove dead copper): 3005.12,4235.37 3759.19,4235.37 3861.57,4325.69 3861.57,4430.69 4572.68,4430.69 4572.68,3064.83 3011.35,3064.83
GND on Bottom Layer (solid, remove dead copper, pour order 2): 3005.12,4235.37 3758.67,4235.37 3856.57,4330.69 3856.57,4435.69 4567.68,4435.69 4567.68,3069.83 3006.35,3069.83

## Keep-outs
Board Outline Layer:
  region: 3005.12,4439.3 3605.36,4439.3 3605.36,4235.37 3005.12,4235.37
  lines w10: 3000,3066.48 4574.8,3066.48 4574.8,4444.43 3000,4444.43 3000,3066.48

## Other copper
Top Layer:
  region net GND: 3534.19,4235.33 3593.55,4235.33 3593.55,4192.02 3534.19,4192.02
  region net GND: 3038.98,4253.33 3038.98,4408.45 3105.91,4408.45 3105.91,4304.51 3224.02,4304.51 3224.02,4408.45 3290.95,4408.45 3290.95,4304.51 3409.06,4304.51 3409.06,4408.45 3475.99,4408.45 3475.99,4235.21 3495.67,4235.21 3495.67,4408.45 3550.79,4408.45 3550.79,4235.21 3586.23,4235.21 3586.22,4428.13 3389.37,4428.13 3389.37,4324.19 3310.63,4324.19 3310.63,4428.13 3204.34,4428.13 3204.34,4324.19 3125.59,4324.19 3125.59,4428.13 3019.3,4428.13 3019.3,4253.33
  region net $1N4019: 3475.99,4235.22 3475.99,4215.53 3495.67,4215.53 3495.67,4235.22
  region net GND: 3586.22,4235.22 3586.22,4215.53 3550.79,4215.53 3550.79,4235.22

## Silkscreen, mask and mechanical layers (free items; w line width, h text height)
Top Silkscreen Layer:
  text "BAT+" at 4336.57,4388.05 h39.37
  text "BAT-" at 4341.57,4103.05 h39.37
  text "SWRA117D / Not certified / ESP-PPB  / V5.12" at 3031.57,3983.05 h59.06
  text "Battery" at 4571.57,3183.05 h39.37 r90
  text "5V" at 4256.57,3178.05 h39.37
Bottom Silkscreen Layer:
  text "BAT+ /  / BAT-" at 4561.57,4158.05 h78.74
  text "ESP-PPB / V5.12" at 3554.66,3970.74 h120
  text "SDA /  /  / SCL /  /  / VCC /  /  / GND" at 3211.57,3283.05 h35.43
  text "Battery /  / 5V" at 4301.57,3238.05 h78.74 r270
  text "+5v / GPIO0 / GPIO1 / GPIO10 / GPIO4 / GPIO5 / GPIO8 / GND" at 3481.57,3208.05 h100 r270
  text "ENABLE   DOWNLOAD" at 3451.57,3153.05 h39.37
